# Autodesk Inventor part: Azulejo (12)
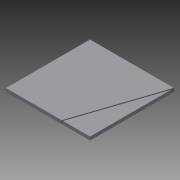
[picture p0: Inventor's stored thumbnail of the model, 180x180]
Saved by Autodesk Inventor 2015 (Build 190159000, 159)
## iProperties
Created: 2015-04
Part Number: Azulejo (12)
Material: Genérico
Document SubType Name: Modeling
Designer: Felipe
Density: 1 g/cm^3
Appearance: Padrão
Author: Felipe
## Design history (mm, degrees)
sketch "Sketch1"
  geometry: L1 (-1510, -7490)-(-1510, -6010); L2 (992.445, 7510)-(992.445, 8990); L3 (1012.445, 7510)-(1012.445, 8990); L4 (-3010, 4510)-(-3010, 5990); L5 (-3010, -1490)-(-3010, -10); L6 (-1510, 7490)-(-2990, 7490); L7 (-2990, 5990)-(-2990, 4510); L8 (-2990, 10)-(-1510, 10); L9 (-1510, -10)-(-2990, -10); L10 (-1510, -1490)-(-1510, -10); L11 (-3010, 7490)-(-4490, 7490); L12 (-3010, 5990)-(-4490, 5990); L13 (-10, 9010)-(-10, 10490); L14 (-10, 7510)-(-10, 8990); L15 (-10, 7490)-(-1490, 7490); L16 (-1490, 6010)-(-10, 6010); L17 (-10, 5990)-(-1490, 5990); L18 (-1490, 5990)-(-1490, 4510); L19 (-1490, -10)-(-1490, -1490); L20 (-1490, -1490)-(-10, -1490); L21 (-10, -1510)-(-1490, -1510); L22 (-10, -2990)-(-10, -1510); L23 (-10, -5990)-(-10, -4510); L24 (-1490, -7490)-(-10, -7490); L25 (10, 8990)-(10, 7510); L26 (1490, 7510)-(1490, 8990); L27 (10, 6010)-(1490, 6010); L28 (1490, 6010)-(1490, 7490); L29 (1490, 5990)-(10, 5990); L30 (4490, -6010)-(3010, -6010); L31 (10, -1510)-(10, -2990); L32 (10, -3010)-(10, -4490); L33 (10, -4510)-(10, -5990); L34 (10, -5990)-(1490, -5990); L35 (1490, -6010)-(10, -6010); L36 (10, -7490)-(1490, -7490); L37 (2990, 9010)-(2990, 10490); L38 (1510, 8990)-(1510, 7510); L39 (1510, 7510)-(2990, 7510); L40 (2990, 7490)-(1510, 7490); L41 (1510, 7490)-(1510, 6010); L42 (1510, -5990)-(2990, -5990); L43 (2990, -6010)-(1510, -6010); L44 (1510, -7490)-(2990, -7490); L45 (3010, 10490)-(3010, 9010); L46 (3010, 9010)-(4490, 9010); L47 (4490, 8990)-(3010, 8990); L48 (4490, 7490)-(3010, 7490); L49 (4490, 1510)-(4490, 2990); L50 (4490, 10)-(4490, 1490); L51 (4490, -1490)-(4490, -10); L52 (4490, -2990)-(4490, -1510); L53 (3010, -5990)-(4490, -5990); L54 (3010, -7490)-(4490, -7490); L55 (4510, 9010)-(5990, 9010); L56 (5990, 8990)-(4510, 8990); L57 (4510, 7510)-(5990, 7510); L58 (5990, 7490)-(4510, 7490); L59 (4510, 3010)-(5990, 3010); L60 (5990, 2990)-(4510, 2990); L61 (4510, 2990)-(4510, 1510); L62 (4510, 1510)-(5990, 1510); L63 (5990, 1510)-(5990, 1740.185); L64 (5990, 1760.2)-(5990, 2259.8)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; A1 r 250 centre (6000, 2010) between (5990, 2259.8) and (5990, 1760.2); A2 r 250 centre (6000, 2010) between (6010, 1760.2) and (6010, 2259.8); A3 r 270 centre (6000, 2010) between (5990, 2279.815) and (5990, 1740.185); A4 r 270 centre (6000, 2010) between (6010, 1740.185) and (6010, 2279.815); A5 r 3010.017 centre (0, 0) between (-1490, -2615.358) and (-346.554, -2990); A6 r 2990.017 centre (0, 0) between (-1490, -2592.316) and (-10, -2990); A7 r 3010.017 centre (0, 0) between (-2603.863, -1510) and (-1510, -2603.863); A8 r 2990.017 centre (0, 0) between (-2580.717, -1510) and (-1510, -2580.717); A9 r 3010.017 centre (0, 0) between (-2990, -346.554) and (-2615.358, -1490); A10 r 2990.017 centre (0, 0) between (-2990, -10) and (-2592.316, -1490); A11 r 2131.367 centre (7500, -1500) between (7490, 631.344) and (6010, 24.017); A12 r 2131.367 centre (7500, -1500) between (5975.983, -10) and (5368.656, -1490); A13 r 2131.367 centre (7500, -1500) between (5368.656, -1510) and (5975.983, -2990); A14 r 2131.367 centre (7500, -1500) between (6010, -3024.017) and (7190, -3608.703); A15 r 1831.367 centre (7500, -1500) between (7490.321, 331.342) and (6463.753, 10); A16 r 1831.367 centre (7500, -1500) between (6435.196, -10) and (6010, -435.196); A17 r 1831.367 centre (7500, -1500) between (5990, -463.753) and (5668.66, -1490); A18 r 1831.367 centre (7500, -1500) between (5668.66, -1510) and (5990, -2536.247); A19 r 1831.367 centre (7500, -1500) between (6010, -2564.804) and (6435.196, -2990); A20 r 1831.367 centre (7500, -1500) between (6463.753, -3010) and (7490, -3331.34); A21 r 2111.367 centre (7500, -1500) between (7490.047, 611.344) and (6024.272, 10); A22 r 2111.367 centre (7500, -1500) between (5990, -24.272) and (5388.656, -1490); A23 r 2111.367 centre (7500, -1500) between (5388.656, -1510) and (5990, -2975.728); A24 r 2111.367 centre (7500, -1500) between (6024.272, -3010) and (7210, -3591.357); A25 r 1811.367 centre (7500, -1500) between (7490.374, 311.342) and (6499.524, 10); A26 r 1811.367 centre (7500, -1500) between (6469.975, -10) and (6010, -469.975); A27 r 1811.367 centre (7500, -1500) between (5990, -499.524) and (5688.66, -1490); A28 r 1811.367 centre (7500, -1500) between (5688.66, -1510) and (5990, -2500.476); A29 r 1811.367 centre (7500, -1500) between (6010, -2530.025) and (6469.975, -2990); A30 r 1811.367 centre (7500, -1500) between (6499.524, -3010) and (7490, -3311.34); A31 r 449.871 centre (7499.449, -4060.672) between (7510, -4510.419) and (7521.546, -4510); 3 further points
  constraints: 1086 end point, 64 point on circle, 31 centre point, 13 point on line, 1 other
extrude "Extrusion1" new body sketch "Sketch1" distance "d0" = 60; taper "d1" = 0 deg
extrude "Extrusion2" new body sketch "Sketch1" distance "d2" = 60; taper "d3" = 0 deg
body "Solid1"
body "Solid2"
